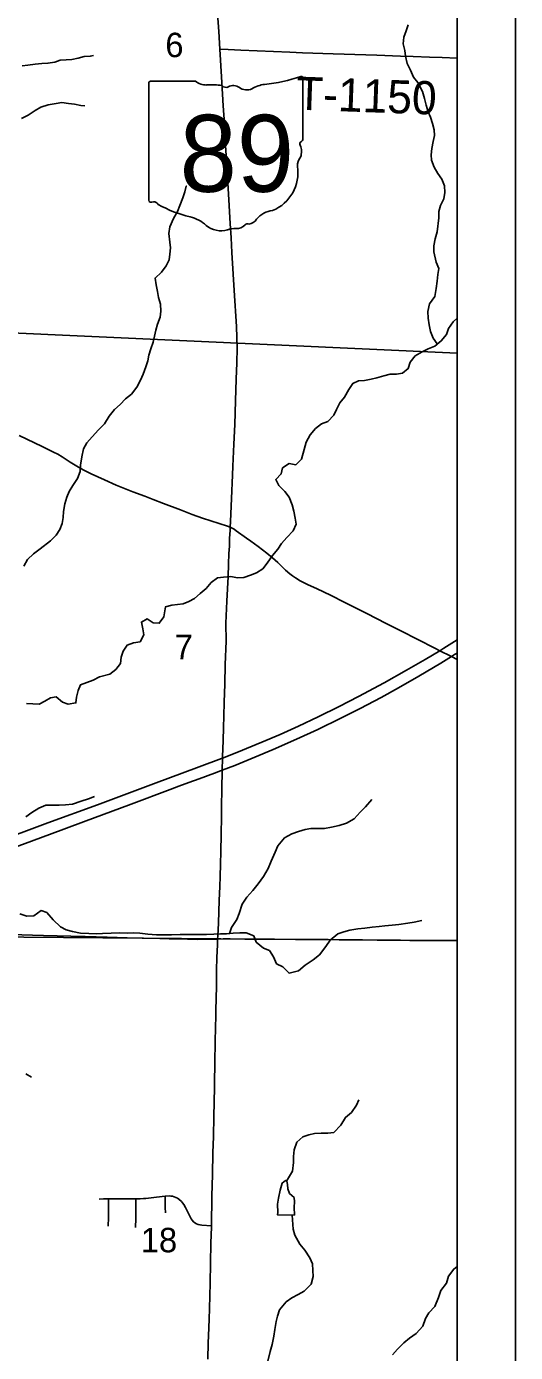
# Model space of a CAD drawing. Extents: x 0 to 34, y 0 to 22.
# Drawn here: x 19.303 to 20.14, y 17.453 to 19.726 of the extents above; entities that cross this region are included whole.
import ezdxf

# ---------------------------------------------------------------- set-up
doc = ezdxf.new("R2010")
doc.units = 0
for name, color, linetype in [('GM_X_County_Road', 7, 'Continuous'), ('GM_X_Interstate_Route', 7, 'Continuous'), ('GM_X_Minor_Lake', 7, 'Continuous'), ('GM_X_Minor_River', 7, 'Continuous'), ('GM_X_Rail_Line', 7, 'Continuous'), ('GM_X_Section_Text', 7, 'Continuous'), ('GM_X_State_Location', 7, 'Continuous'), ('GM_X_State_Route', 7, 'Continuous'), ('GM_X_State_Shield', 7, 'Continuous'), ('GM_X_Township_Road', 7, 'Continuous'), ('GM_X_Township_Road_Text', 7, 'Continuous'), ('GM_X_US_Shield', 7, 'Continuous'), ('SH_Data', 7, 'Continuous')]:
    doc.layers.add(name, color=color, linetype=linetype)

msp = doc.modelspace()

# ---------------------------------------------------------------- linework, layer by layer
at = {"layer": 'GM_X_County_Road'}
for points in [[(19.2766, 18.1698), (19.3325, 18.1681), (19.3791, 18.167), (19.4039, 18.1662), (19.4412, 18.1648), (19.4754, 18.1639), (19.5033, 18.1634), (19.5317, 18.1626), (19.5476, 18.1623), (19.564, 18.162), (19.579, 18.1616), (19.5968, 18.1611), (19.6212, 18.1616), (19.6305, 18.1618)], [(19.6305, 18.1618), (19.6398, 18.1621), (19.6522, 18.1621), (19.677, 18.1619), (19.6987, 18.1617), (19.7278, 18.1615), (19.764, 18.1613), (19.7897, 18.1611), (19.8196, 18.1609), (19.8445, 18.1604), (19.86, 18.1604), (19.8786, 18.1605), (19.9034, 18.1602), (19.9438, 18.1599), (19.9593, 18.1596), (19.981, 18.1594), (19.9965, 18.1593), (20.0151, 18.1592), (20.0404, 18.1591)]]:
    msp.add_lwpolyline(points, dxfattribs=at)
at = {"layer": 'GM_X_Interstate_Route'}
for points in [[(19.2787, 18.338), (19.3079, 18.3488), (19.3399, 18.3607), (19.4245, 18.3919), (19.5204, 18.428), (19.5991, 18.457), (19.637, 18.4711), (19.639, 18.4718), (19.6631, 18.4813), (19.7062, 18.499), (19.7376, 18.5125), (19.7688, 18.5266), (19.8025, 18.5426), (19.8388, 18.5604), (19.8719, 18.5775), (19.9157, 18.6011), (19.9537, 18.6224), (19.986, 18.641), (20.0108, 18.656), (20.0179, 18.6604), (20.0404, 18.6744)], [(19.6355, 18.4502), (19.6383, 18.4513), (19.6597, 18.4595), (19.6943, 18.4733), (19.7258, 18.4866), (19.7655, 18.5042), (19.8021, 18.5212), (19.8412, 18.5403), (19.8744, 18.5571), (19.9102, 18.5758), (19.9401, 18.5922), (19.9752, 18.6123), (20.0126, 18.6344), (20.0308, 18.6458), (20.0362, 18.6492), (20.0404, 18.6519)], [(19.2171, 18.2949), (19.3424, 18.3412), (19.4007, 18.3627), (19.4823, 18.3931), (19.5493, 18.4179), (19.5638, 18.4236), (19.5813, 18.4301), (19.5988, 18.4363), (19.625, 18.4461), (19.6355, 18.4502)]]:
    msp.add_lwpolyline(points, dxfattribs=at)
at = {"layer": 'GM_X_Minor_Lake'}
for points in [[(19.7621, 17.6889), (19.7617, 17.7025), (19.7621, 17.7116), (19.7613, 17.7188), (19.7575, 17.7222), (19.7533, 17.726), (19.7506, 17.734), (19.7502, 17.7415), (19.749, 17.7468), (19.7464, 17.748), (19.7407, 17.7438), (19.7373, 17.7316), (19.7347, 17.718), (19.7332, 17.7077), (19.7333, 17.6933)], [(19.7621, 17.6888), (19.7617, 17.7025), (19.7621, 17.7116), (19.7613, 17.7188), (19.7575, 17.7222), (19.7533, 17.726), (19.7506, 17.734), (19.7502, 17.7415), (19.749, 17.7468), (19.7464, 17.748), (19.7407, 17.7438), (19.7373, 17.7316), (19.7347, 17.718), (19.7332, 17.7077), (19.7333, 17.6933)], [(19.7333, 17.6933), (19.7331, 17.6891), (19.7621, 17.6889)]]:
    msp.add_lwpolyline(points, dxfattribs=at)
at = {"layer": 'GM_X_Minor_River'}
for points in [[(20.0066, 19.1815), (19.9993, 19.1916), (19.9952, 19.2027), (19.9927, 19.2141), (19.9909, 19.2258), (19.9906, 19.2372), (19.9934, 19.2505), (20.0022, 19.2629), (20.0049, 19.2766), (20.0066, 19.2891), (20.0074, 19.3008), (20.009, 19.3111), (20.0046, 19.3217), (20.0009, 19.3392), (20.0006, 19.3498), (20.003, 19.3616), (20.0065, 19.3737), (20.009, 19.3979), (20.0091, 19.4086), (20.0122, 19.4188), (20.018, 19.4305), (20.0192, 19.4411), (20.0189, 19.4525), (20.0141, 19.4639), (20.0074, 19.4738), (20.001, 19.4845), (19.9966, 19.4963), (19.9959, 19.5058), (19.9971, 19.5164), (19.9995, 19.5286), (20.0015, 19.5388), (20.0012, 19.5487), (19.9986, 19.5593), (19.9949, 19.57), (19.9909, 19.5795), (19.9875, 19.5905), (19.9846, 19.6019), (19.9813, 19.6141), (19.9735, 19.6294), (19.9656, 19.6389), (19.9604, 19.6508), (19.9552, 19.6622), (19.9523, 19.6747), (19.9508, 19.6842), (19.9483, 19.696), (19.9491, 19.7074), (19.9534, 19.7184), (19.9569, 19.7282)], [(19.2959, 19.6584), (19.3054, 19.6594), (19.3179, 19.6608), (19.3297, 19.6622), (19.3399, 19.6625), (19.3516, 19.6647), (19.3611, 19.668), (19.371, 19.6686), (19.3808, 19.6689), (19.3918, 19.6711), (19.4021, 19.6744), (19.4123, 19.6747), (19.418, 19.6758)], [(19.2944, 19.5677), (19.3058, 19.5736), (19.318, 19.5815), (19.3279, 19.5871), (19.3404, 19.5911), (19.3541, 19.5937), (19.3639, 19.5951), (19.3753, 19.5938), (19.3851, 19.5922), (19.3961, 19.5902), (19.4029, 19.5894)], [(19.5109, 19.1527), (19.5125, 19.1626), (19.516, 19.1732), (19.5202, 19.1845), (19.5226, 19.1951), (19.5246, 19.205), (19.5273, 19.2152), (19.532, 19.2277), (19.5332, 19.2375), (19.5329, 19.2497), (19.5292, 19.2611), (19.5274, 19.2717), (19.5252, 19.2831), (19.5234, 19.2945), (19.5341, 19.3047), (19.5426, 19.3152), (19.5472, 19.3258), (19.5488, 19.3356), (19.55, 19.3463), (19.5486, 19.3558), (19.5468, 19.371), (19.5484, 19.3823), (19.555, 19.3967), (19.5615, 19.4084), (19.5658, 19.4186), (19.5708, 19.4318), (19.5743, 19.4424), (19.5767, 19.4522), (19.5767, 19.4519)], [(19.7583, 18.906), (19.7528, 18.9193), (19.7453, 18.9289), (19.7351, 18.9392), (19.7299, 18.9491), (19.7395, 18.9589), (19.7418, 18.9691), (19.7532, 18.9766), (19.7646, 18.9746), (19.7738, 18.9844), (19.7784, 19.0006), (19.7823, 19.0131), (19.7889, 19.026), (19.7981, 19.0365), (19.8083, 19.0447), (19.8194, 19.0488), (19.8297, 19.0593), (19.8339, 19.0695), (19.8397, 19.0809), (19.8474, 19.0906), (19.855, 19.1035), (19.8619, 19.1137), (19.8718, 19.1185), (19.8817, 19.1188), (19.8931, 19.1213), (19.9029, 19.1235), (19.9151, 19.1272), (19.9261, 19.1297), (19.9367, 19.1296), (19.9469, 19.1314), (19.9568, 19.1393), (19.9603, 19.1503), (19.9688, 19.1612), (19.9809, 19.1679), (19.9908, 19.1735), (20.0022, 19.1779), (20.0133, 19.1869), (20.0225, 19.1978), (20.0259, 19.2081), (20.034, 19.2197), (20.0404, 19.226)], [(19.2989, 18.8008), (19.3047, 18.8121), (19.315, 18.8219), (19.3264, 18.8305), (19.3443, 18.8443), (19.3539, 18.8537), (19.3604, 18.8635), (19.3643, 18.8741), (19.3659, 18.8844), (19.3667, 18.8942), (19.3691, 18.9075), (19.3722, 18.9192), (19.3765, 18.929), (19.3826, 18.9392), (19.3907, 18.9513), (19.3953, 18.963), (19.3958, 18.974), (19.3978, 18.9884), (19.4009, 19.002), (19.4067, 19.0122), (19.4155, 19.0224), (19.4262, 19.0344), (19.4365, 19.0446), (19.4446, 19.0581), (19.4538, 19.0691), (19.4633, 19.0781), (19.4728, 19.0878), (19.4831, 19.0957), (19.4923, 19.1074), (19.4985, 19.1195), (19.5031, 19.1297), (19.5074, 19.1425), (19.5109, 19.1527)], [(19.303, 18.5655), (19.3139, 18.565), (19.3249, 18.5641), (19.3344, 18.5693), (19.3443, 18.5749), (19.3542, 18.5767), (19.3647, 18.5679), (19.3745, 18.5644), (19.3878, 18.5665), (19.3886, 18.5764), (19.3917, 18.5878), (19.3956, 18.5976), (19.4063, 18.6017), (19.4173, 18.6057), (19.4283, 18.6109), (19.4461, 18.6157), (19.456, 18.6239), (19.4641, 18.6341), (19.4653, 18.6451), (19.4688, 18.6553), (19.4753, 18.6655), (19.4863, 18.6692), (19.4977, 18.671), (19.5039, 18.6834), (19.5024, 18.6937), (19.4999, 18.7051), (19.5098, 18.7103), (19.5203, 18.7038), (19.5305, 18.7029), (19.5382, 18.7138), (19.5414, 18.7312), (19.552, 18.7342), (19.5615, 18.7352), (19.5717, 18.7363), (19.5812, 18.74), (19.5907, 18.7456), (19.6003, 18.7538), (19.611, 18.7628), (19.6194, 18.7726), (19.63, 18.7809), (19.6403, 18.7819), (19.6528, 18.7829), (19.6645, 18.7809), (19.6755, 18.7815), (19.6865, 18.7852), (19.6971, 18.7893), (19.7078, 18.7964), (19.7155, 18.8062), (19.7243, 18.819), (19.7334, 18.8299), (19.7396, 18.8397), (19.7488, 18.8499), (19.7598, 18.8612), (19.7649, 18.8729), (19.7634, 18.8831), (19.7609, 18.8953), (19.7583, 18.906)], [(19.3023, 18.3715), (19.3125, 18.3788), (19.3242, 18.3864), (19.3363, 18.391), (19.3591, 18.3911), (19.3701, 18.3919), (19.3822, 18.393), (19.3966, 18.398), (19.4091, 18.4022), (19.4197, 18.4061)], [(19.6506, 18.1713), (19.6541, 18.1818), (19.6635, 18.1955), (19.6673, 18.2057), (19.6722, 18.2217), (19.6805, 18.2338), (19.6907, 18.2452), (19.7001, 18.2563), (19.7092, 18.2692), (19.7167, 18.2829), (19.7224, 18.2954), (19.7288, 18.311), (19.7333, 18.3213), (19.745, 18.335), (19.7575, 18.3422), (19.7689, 18.346), (19.7803, 18.3495), (19.7898, 18.351), (19.803, 18.3515), (19.8137, 18.3515), (19.8254, 18.3534), (19.8387, 18.3565), (19.8512, 18.3603), (19.8644, 18.3676), (19.8743, 18.379), (19.8837, 18.3885), (19.8947, 18.4007)], [(19.2917, 18.2053), (19.3035, 18.2012), (19.316, 18.2016), (19.3285, 18.2107), (19.338, 18.2074), (19.3487, 18.1945), (19.3612, 18.1828), (19.3711, 18.1775), (19.3817, 18.1745), (19.3958, 18.1722), (19.4102, 18.1712), (19.4223, 18.1708), (19.4333, 18.1712), (19.4481, 18.172), (19.4622, 18.1725), (19.4758, 18.1721), (19.4868, 18.1725), (19.4974, 18.1718), (19.5107, 18.1703), (19.5255, 18.1692), (19.5418, 18.1689), (19.5513, 18.1689), (19.5661, 18.1694), (19.5782, 18.1698), (19.6116, 18.1699), (19.6241, 18.1703), (19.6355, 18.1707), (19.6454, 18.1707), (19.6571, 18.1719), (19.6685, 18.1723), (19.6791, 18.1727), (19.6924, 18.1671), (19.6966, 18.1565), (19.7088, 18.1463), (19.7191, 18.1421), (19.7259, 18.1311), (19.7313, 18.1194), (19.7423, 18.1145), (19.7529, 18.1031), (19.7692, 18.1074), (19.7802, 18.1173), (19.7938, 18.1264), (19.8048, 18.1348), (19.8158, 18.1489), (19.8229, 18.1599), (19.8362, 18.1706), (19.8464, 18.1744), (19.8567, 18.1771), (19.8707, 18.1794), (19.8824, 18.1806), (19.8953, 18.1821), (19.9071, 18.1833), (19.9169, 18.1845), (19.9295, 18.1856), (19.9405, 18.1868), (19.956, 18.1888), (19.967, 18.1907)], [(19.967, 18.1907), (19.9799, 18.1938)], [(19.302, 17.931), (19.3115, 17.925)], [(19.7483, 17.7472), (19.7585, 17.7643), (19.7603, 17.7788), (19.7603, 17.789), (19.7614, 17.8008), (19.7659, 17.8137), (19.7765, 17.8228), (19.7867, 17.8266), (19.7962, 17.8286), (19.808, 17.8294), (19.8194, 17.8294), (19.8296, 17.8306), (19.8413, 17.8431), (19.8493, 17.8561), (19.8595, 17.8644), (19.8685, 17.877), (19.8723, 17.8865)], [(19.7162, 17.4386), (19.7203, 17.455), (19.7241, 17.4671), (19.7267, 17.4816), (19.7286, 17.4926), (19.7308, 17.5062), (19.7327, 17.5157), (19.7364, 17.5264), (19.7478, 17.5404), (19.7576, 17.5469), (19.7682, 17.5526), (19.7788, 17.5587), (19.7905, 17.5705), (19.7939, 17.5838), (19.7935, 17.5941), (19.7927, 17.6055), (19.7885, 17.6153), (19.7797, 17.6286), (19.7714, 17.6388), (19.7626, 17.6547), (19.7595, 17.6649), (19.7583, 17.6889)], [(19.9297, 17.4495), (19.9384, 17.4591), (19.9494, 17.4697), (19.9592, 17.4777), (19.9706, 17.4857), (19.9819, 17.4983), (19.9861, 17.5116), (19.9921, 17.5214), (20.0023, 17.5321), (20.0087, 17.5477), (20.0129, 17.5595), (20.0223, 17.572), (20.0257, 17.5842), (20.0348, 17.5963), (20.0404, 17.6005)]]:
    msp.add_lwpolyline(points, dxfattribs=at)
at = {"layer": 'GM_X_Rail_Line'}
msp.add_lwpolyline([(20.0404, 14.169), (20.0404, 20.2202), (19.5489, 20.2208), (19.5137, 20.2208), (19.105, 20.2214), (19.1046, 20.1073), (19.1032, 19.1112), (19.0976, 18.2716), (19.0975, 18.2511), (19.0972, 18.1277), (19.0934, 17.1717), (19.0896, 16.1806), (19.0858, 15.176), (19.082, 14.1642)], close=True, dxfattribs=at)
at = {"layer": 'GM_X_State_Route'}
msp.add_lwpolyline([(19.6139, 17.4419), (19.6145, 17.4698), (19.6148, 17.4822), (19.6157, 17.5102), (19.6163, 17.5289), (19.6176, 17.5724), (19.619, 17.6408), (19.6197, 17.6687), (19.6197, 17.6705), (19.6207, 17.721), (19.6217, 17.7583), (19.6225, 17.7955), (19.6231, 17.8235), (19.6238, 17.8576), (19.6249, 17.9073), (19.6257, 17.957), (19.6261, 17.9786), (19.6264, 17.9877), (19.6267, 18.0093), (19.6271, 18.031), (19.6274, 18.0402), (19.6283, 18.0806), (19.6287, 18.1085), (19.6293, 18.1302), (19.63, 18.152), (19.6305, 18.1618), (19.6308, 18.1675), (19.6317, 18.1892), (19.6323, 18.2092), (19.6332, 18.2278), (19.6342, 18.2519), (19.6347, 18.2688), (19.6354, 18.2899), (19.6361, 18.3117), (19.6367, 18.3409), (19.6371, 18.372), (19.6371, 18.3932), (19.6374, 18.4149), (19.6377, 18.4273), (19.638, 18.4428), (19.6383, 18.4513), (19.639, 18.4718), (19.639, 18.4739), (19.6399, 18.5018), (19.6405, 18.5241), (19.6411, 18.5435), (19.6418, 18.5678), (19.6426, 18.5988), (19.6436, 18.6325), (19.6448, 18.6723), (19.6445, 18.7031), (19.6462, 18.7409), (19.6471, 18.762), (19.6483, 18.7831), (19.6491, 18.8045), (19.6498, 18.8223), (19.6505, 18.8348), (19.651, 18.8488), (19.6518, 18.8622), (19.6521, 18.8674), (19.6527, 18.8772), (19.6543, 18.9168), (19.656, 18.957), (19.6567, 18.9724), (19.6584, 19.0097), (19.6598, 19.0438), (19.6613, 19.0841), (19.6624, 19.1214), (19.6635, 19.1493), (19.6638, 19.1741), (19.6635, 19.1927), (19.6627, 19.2113), (19.6589, 19.2733), (19.657, 19.3012), (19.6549, 19.3384), (19.6534, 19.3632), (19.6519, 19.388), (19.6494, 19.4283), (19.6461, 19.4873), (19.644, 19.5214), (19.6421, 19.5586), (19.6401, 19.5896), (19.6372, 19.6392), (19.6344, 19.6867), (19.6325, 19.7168), (19.6291, 19.7632)], dxfattribs=at)
at = {"layer": 'GM_X_State_Shield'}
for p, q in [((19.5925, 19.6317), (19.5153, 19.6317)), ((19.7764, 19.532), (19.7764, 19.6367)), ((19.5127, 19.6283), (19.5127, 19.4281)), ((19.7763, 19.532), (19.7764, 19.532))]:
    msp.add_line(p, q, dxfattribs=at)
for centre, radius, start, end in [((19.5157, 19.6287), 0.00305, 98.1301, 188.1301), ((19.6109, 19.6549), 0.0296, 231.6195, 271.1119), ((19.6824, 19.9045), 0.2796, 275.8445, 288.9065), ((19.7734, 19.6371), 0.00294, 351.8621, 97.738), ((19.6207, 19.5194), 0.1064, 80.4867, 94.9883), ((19.6449, 19.6297), 0.00855, 219.7921, 297.1024), ((19.6574, 19.6066), 0.0178, 54.4667, 119.1411), ((19.6803, 19.6383), 0.0214, 233.8562, 294.8282), ((19.7181, 19.5706), 0.0563, 97.3462, 120.7689), ((19.7757, 19.5243), 0.00454, 107.944, 210.337), ((19.7468, 19.5111), 0.0273, 340.033, 23.6496), ((19.7732, 19.5316), 0.00314, 289.6038, 7.7341), ((19.7869, 19.4882), 0.0198, 136.8065, 186.9296), ((19.6981, 19.4749), 0.0699, 292.3089, 8.9858), ((19.5157, 19.4277), 0.00308, 171.9584, 258.3066), ((19.5162, 19.4482), 0.0235, 267.339, 280.6039), ((19.521, 19.4166), 0.00848, 29.7484, 93.2717), ((19.6281, 19.5964), 0.2019, 240.4129, 257.1985), ((19.7276, 19.372), 0.0383, 94.4031, 142.5768), ((19.5679, 19.3382), 0.0632, 47.1842, 75.836), ((19.6362, 19.4156), 0.0401, 230.7004, 286.2918), ((19.6623, 19.4006), 0.0214, 268.777, 315.5493), ((19.6816, 19.3812), 0.00601, 65.7517, 132.6484), ((19.6791, 19.4087), 0.0226, 282.8732, 323.2771), ((19.6594, 19.3464), 0.0329, 85.6951, 111.2099)]:
    msp.add_arc(centre, radius, start, end, dxfattribs=at)
at = {"layer": 'GM_X_Township_Road'}
for points in [[(19.6344, 19.6867), (19.6484, 19.686), (19.6701, 19.6849), (19.754, 19.6814), (19.7757, 19.6806), (19.8285, 19.679), (19.8844, 19.6769), (19.9033, 19.6762), (19.9434, 19.6748), (19.9651, 19.6741), (19.9931, 19.6732), (20.0149, 19.6723), (20.0404, 19.6711)], [(19.2909, 19.0246), (19.3303, 19.0059), (19.3417, 19.0004), (19.3497, 18.9964), (19.3567, 18.9925), (19.364, 18.9879), (19.3777, 18.9792), (19.3891, 18.9723), (19.4002, 18.9658), (19.4142, 18.959), (19.4368, 18.9487), (19.4566, 18.9397), (19.4738, 18.9325), (19.4854, 18.9281), (19.5058, 18.9206), (19.5203, 18.9151), (19.5377, 18.9083), (19.5667, 18.8972), (19.587, 18.8894), (19.6046, 18.8832), (19.6474, 18.8694), (19.6521, 18.8674)], [(19.6521, 18.8674), (19.6543, 18.8666), (19.6586, 18.864), (19.6623, 18.8616), (19.6798, 18.849), (19.6873, 18.8435), (19.6998, 18.8344), (19.7146, 18.8231), (19.7242, 18.8151), (19.7334, 18.8068), (19.7469, 18.7941), (19.7539, 18.7879), (19.7587, 18.7841), (19.7638, 18.7806), (19.7718, 18.7759), (19.7857, 18.7691), (19.7997, 18.7625), (19.8248, 18.7503), (19.847, 18.7392), (19.8859, 18.7197), (19.919, 18.7027), (19.9439, 18.6898), (20.0021, 18.6605), (20.0108, 18.656), (20.0298, 18.6463), (20.0308, 18.6458), (20.0404, 18.6408)], [(19.4274, 17.7162), (19.4348, 17.7164), (19.4413, 17.7165), (19.4434, 17.7165)], [(19.4431, 17.6697), (19.4434, 17.6849), (19.4436, 17.697), (19.4434, 17.7092), (19.4434, 17.7165)], [(19.4434, 17.7165), (19.4551, 17.7167), (19.4828, 17.7164), (19.4905, 17.7164)], [(19.4899, 17.6676), (19.4903, 17.6832), (19.4904, 17.7082), (19.4905, 17.7164)], [(19.4905, 17.7164), (19.4926, 17.7164), (19.4979, 17.7166), (19.5035, 17.717), (19.5078, 17.7174), (19.526, 17.7194), (19.5408, 17.7211)], [(19.5411, 17.6927), (19.5407, 17.7019), (19.5408, 17.7142), (19.5408, 17.7211)], [(19.5408, 17.7211), (19.5474, 17.7216), (19.5504, 17.7215), (19.5534, 17.721), (19.5562, 17.7202), (19.559, 17.719), (19.5616, 17.7176), (19.564, 17.7159), (19.5686, 17.7119), (19.5705, 17.7097), (19.5723, 17.7072), (19.5753, 17.702), (19.582, 17.6881), (19.585, 17.6825), (19.5868, 17.6799), (19.589, 17.6775), (19.5915, 17.6755), (19.5942, 17.6739), (19.5972, 17.6727), (19.6003, 17.6719), (19.6035, 17.6714), (19.6197, 17.6705)]]:
    msp.add_lwpolyline(points, dxfattribs=at)
at = {"layer": 'GM_X_US_Shield'}
for points in [[(20.0404, 19.1656), (20.0404, 20.2192), (19.9979, 20.2201), (19.1087, 20.2254), (19.1017, 19.2088)], [(20.0404, 18.1586), (20.0404, 19.1656), (19.1017, 19.2088), (19.1009, 19.202), (19.0964, 18.1818), (19.0961, 18.167)], [(20.0404, 17.1473), (20.0404, 18.1586), (19.0961, 18.167), (19.0893, 17.1816), (19.0897, 17.1649)]]:
    msp.add_lwpolyline(points, close=True, dxfattribs=at)
at = {"layer": 'SH_Data'}
for p, q in [((20.1404, 21), (20.1404, 14)), ((20.0404, 20.9), (20.0404, 14.1))]:
    msp.add_line(p, q, dxfattribs=at)

# ---------------------------------------------------------------- texts
at = {"layer": 'GM_X_Section_Text'}
for s, height, p in [('6', 0.0419, (19.5409, 19.673)), ('7', 0.0419, (19.5568, 18.6414)), ('18', 0.04186, (19.4989, 17.6251))]:
    msp.add_text(s, height=height, rotation=0, dxfattribs=at).set_placement(p)
at = {"layer": 'GM_X_State_Location'}
msp.add_text('89', height=0.000189, rotation=0, dxfattribs=at).set_placement((19.5939, 19.5011))
for s, p in [('s', (19.6416, 19.5149)), ('r', (19.6415, 19.5149))]:
    msp.add_text(s, height=0.000189, dxfattribs=at).set_placement(p)
at = {"layer": 'GM_X_State_Shield'}
msp.add_text('89', height=0.13184, dxfattribs=at).set_placement((19.5653, 19.4423))
at = {"layer": 'GM_X_Township_Road_Text'}
msp.add_text('T-1150', height=0.05682, rotation=357.944, dxfattribs=at).set_placement((19.7639, 19.5831))

doc.saveas('drawing.dxf')
